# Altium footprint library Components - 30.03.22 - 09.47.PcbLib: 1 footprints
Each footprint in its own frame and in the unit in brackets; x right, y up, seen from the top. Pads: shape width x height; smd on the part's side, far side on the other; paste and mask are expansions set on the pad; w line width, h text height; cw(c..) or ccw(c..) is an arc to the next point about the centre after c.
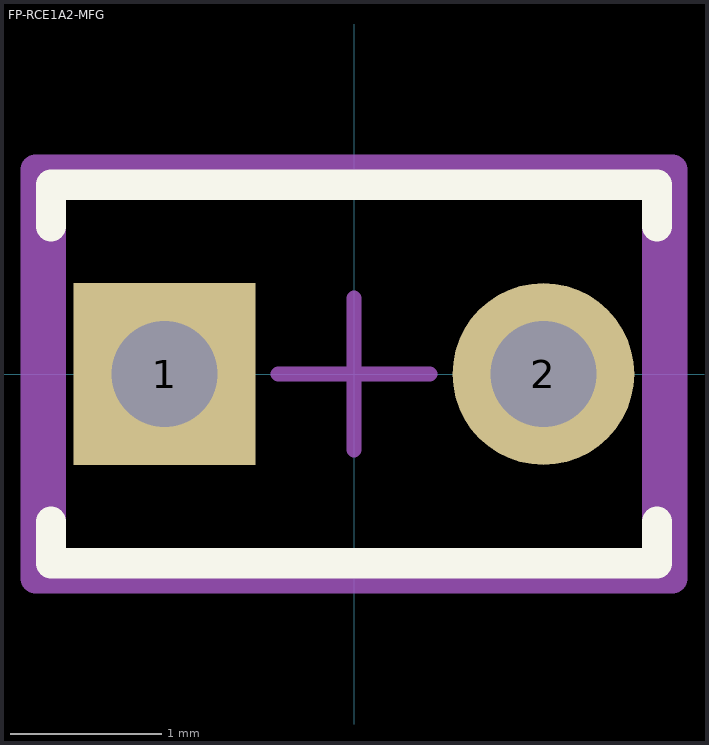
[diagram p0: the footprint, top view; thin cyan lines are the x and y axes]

## FP-RCE1A2-MFG [mm]
pads (2):
  rect 1.2x1.2 hole 0.7 paste-1000 mask+0: 1(-1.25,0)
  round 1.2 hole 0.7 paste-1000 mask+0: 2(1.25,0)
Top Overlay:
  lines w0.2: -2,-0.975 -2,-1.25 2,-1.25 2,-0.975 ; -2,0.975 -2,1.25 2,1.25 2,0.975
Top Assembly:
  lines w0.2: -2.1,-1.35 -2.1,1.35 2.1,1.35 2.1,-1.35 -2.1,-1.35
  text ".Designator" at 0,0.188 h1
Top 3D Body:
  lines w0.2: -2,-1.25 -2,1.25 2,1.25 2,-1.25 -2,-1.25
Top Courtyard:
  lines w0.2: -2.1,-1.35 -2.1,1.35 2.1,1.35 2.1,-1.35 -2.1,-1.35
Top Component Center:
  lines w0.1: -0.5,0 0.5,0 ; 0,-0.5 0,0.5
3D body "Cap_Murata_RCER71E684K1DBH03A_eec.STEP": height 0.25, standoff 0, extent -2.1,-1.35 2.1,1.35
